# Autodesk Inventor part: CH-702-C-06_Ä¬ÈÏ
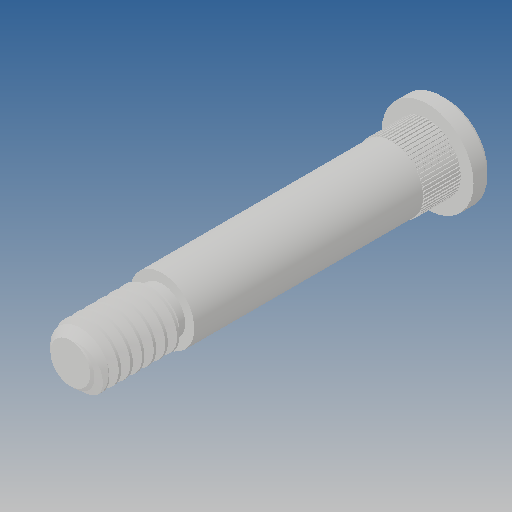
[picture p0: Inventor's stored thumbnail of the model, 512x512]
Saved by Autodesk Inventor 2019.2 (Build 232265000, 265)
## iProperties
Created: 2010-06
Part Number: CH-702-C-06_Ä¬ÈÏ
Material: Ogólny
Document SubType Name: Modeling
Designer: CADENGINEERING4
Density: 1 g/cm^3
Appearance: Domyślna
Author: CADENGINEERING4
Revision Number: ÈÎºÎ
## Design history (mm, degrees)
feature "NONE"
node "Bryła1"
